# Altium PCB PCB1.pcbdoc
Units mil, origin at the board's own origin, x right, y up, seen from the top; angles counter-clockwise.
Board outline 3897.64 x 2283.46 mil, 4 copper layers (Top Layer, Inner1, Inner2, Bottom Layer), stack 62.447 mil thick; 82 components, 48 nets, 260 pads, 205 vias.
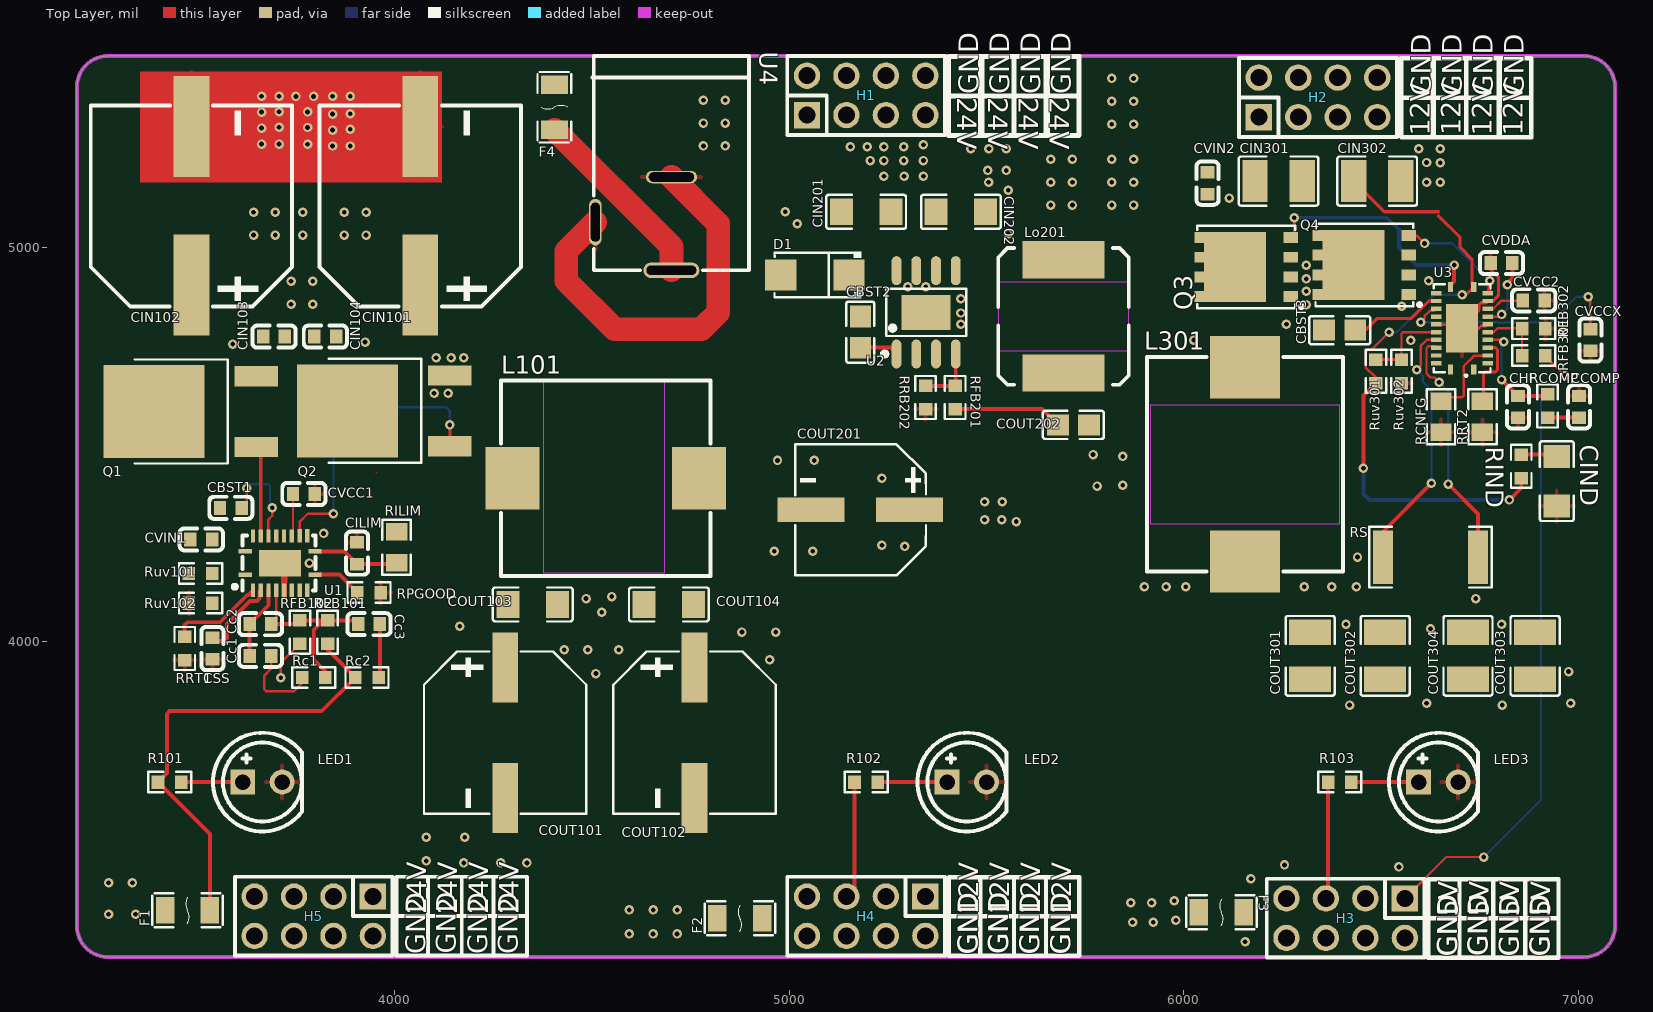
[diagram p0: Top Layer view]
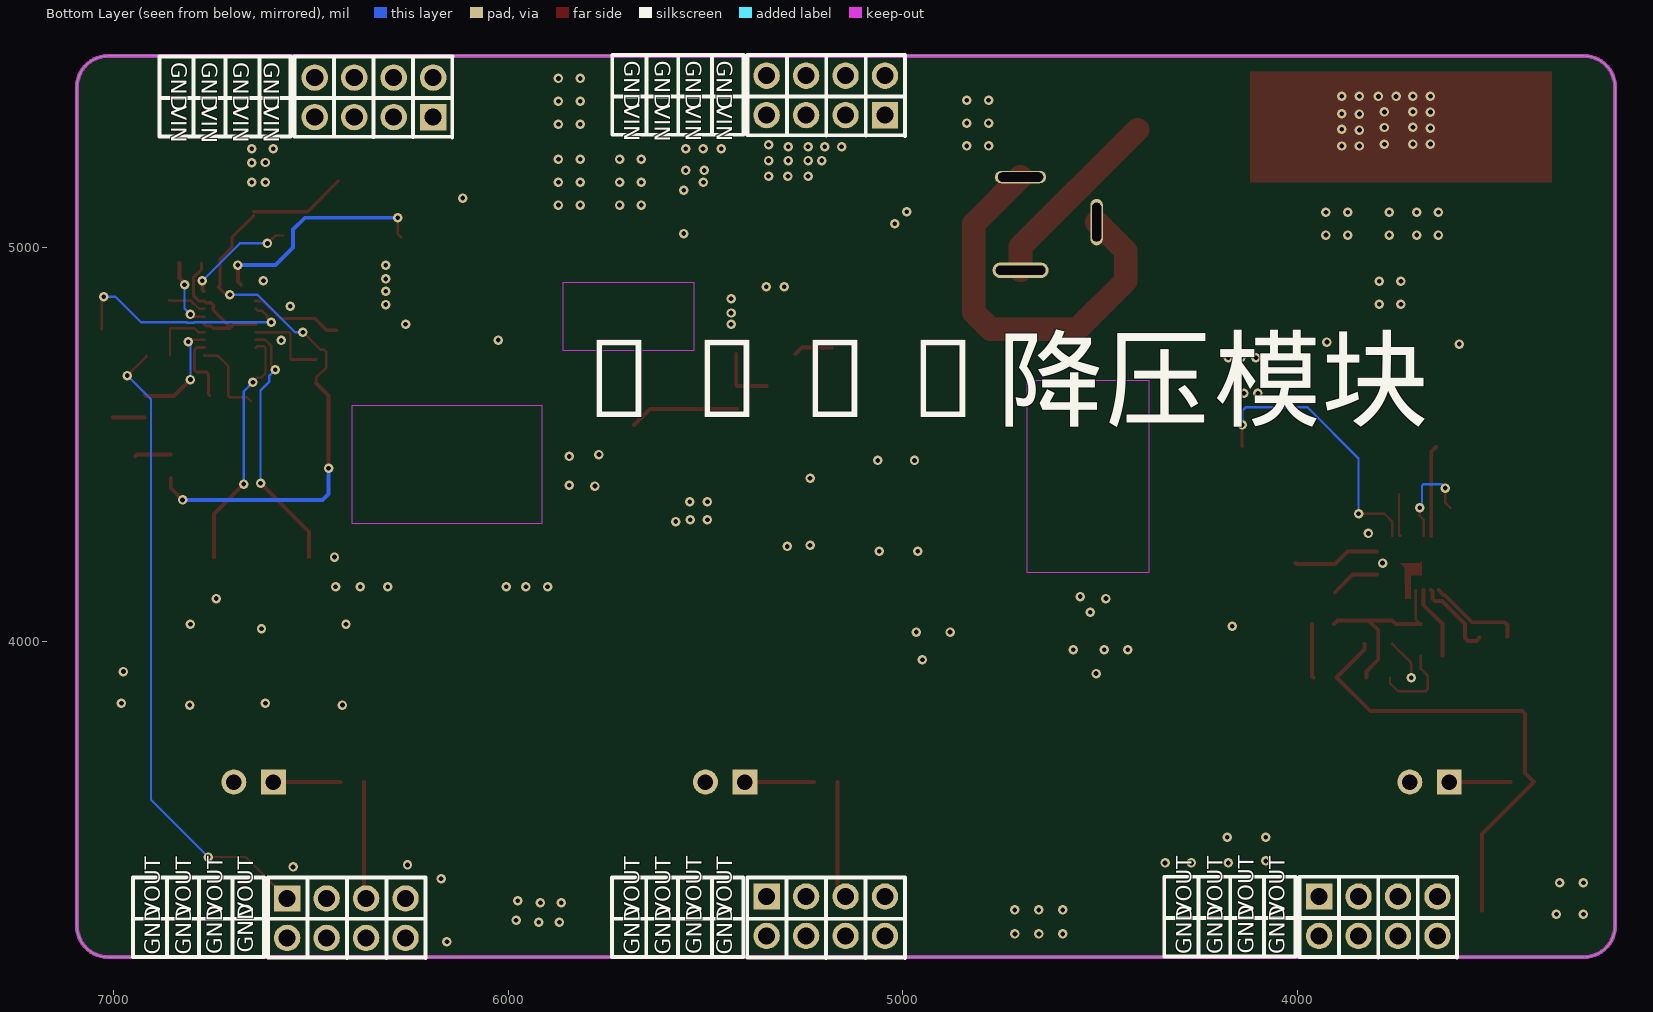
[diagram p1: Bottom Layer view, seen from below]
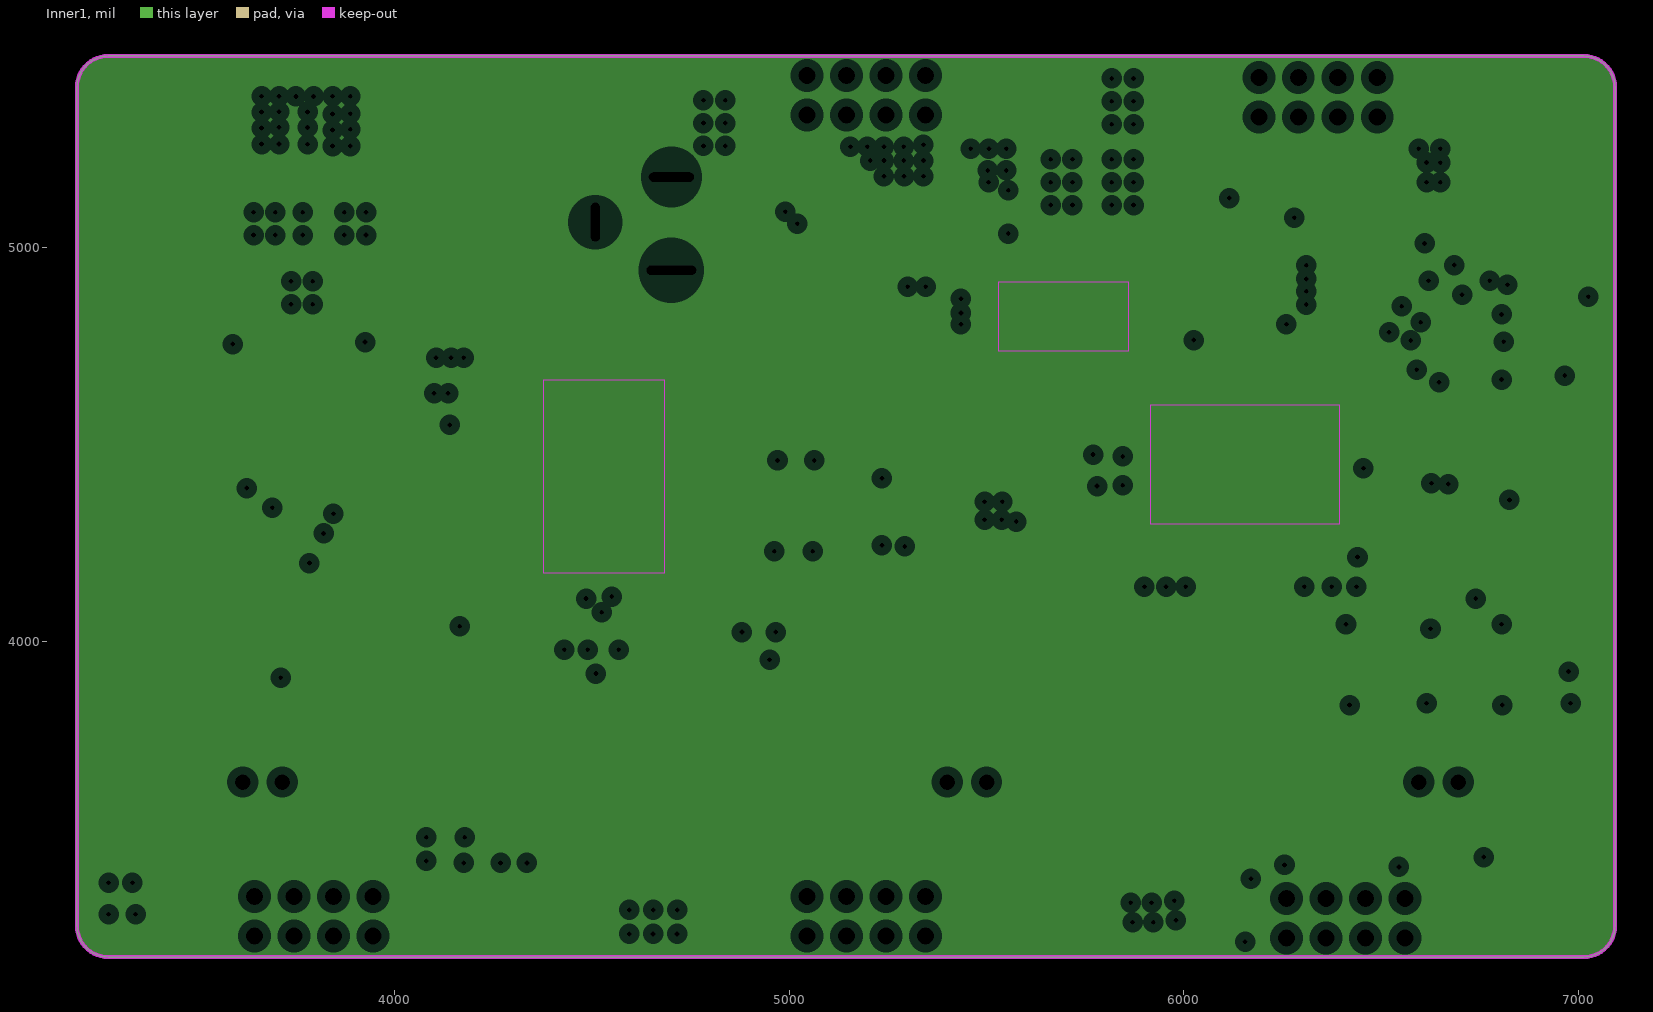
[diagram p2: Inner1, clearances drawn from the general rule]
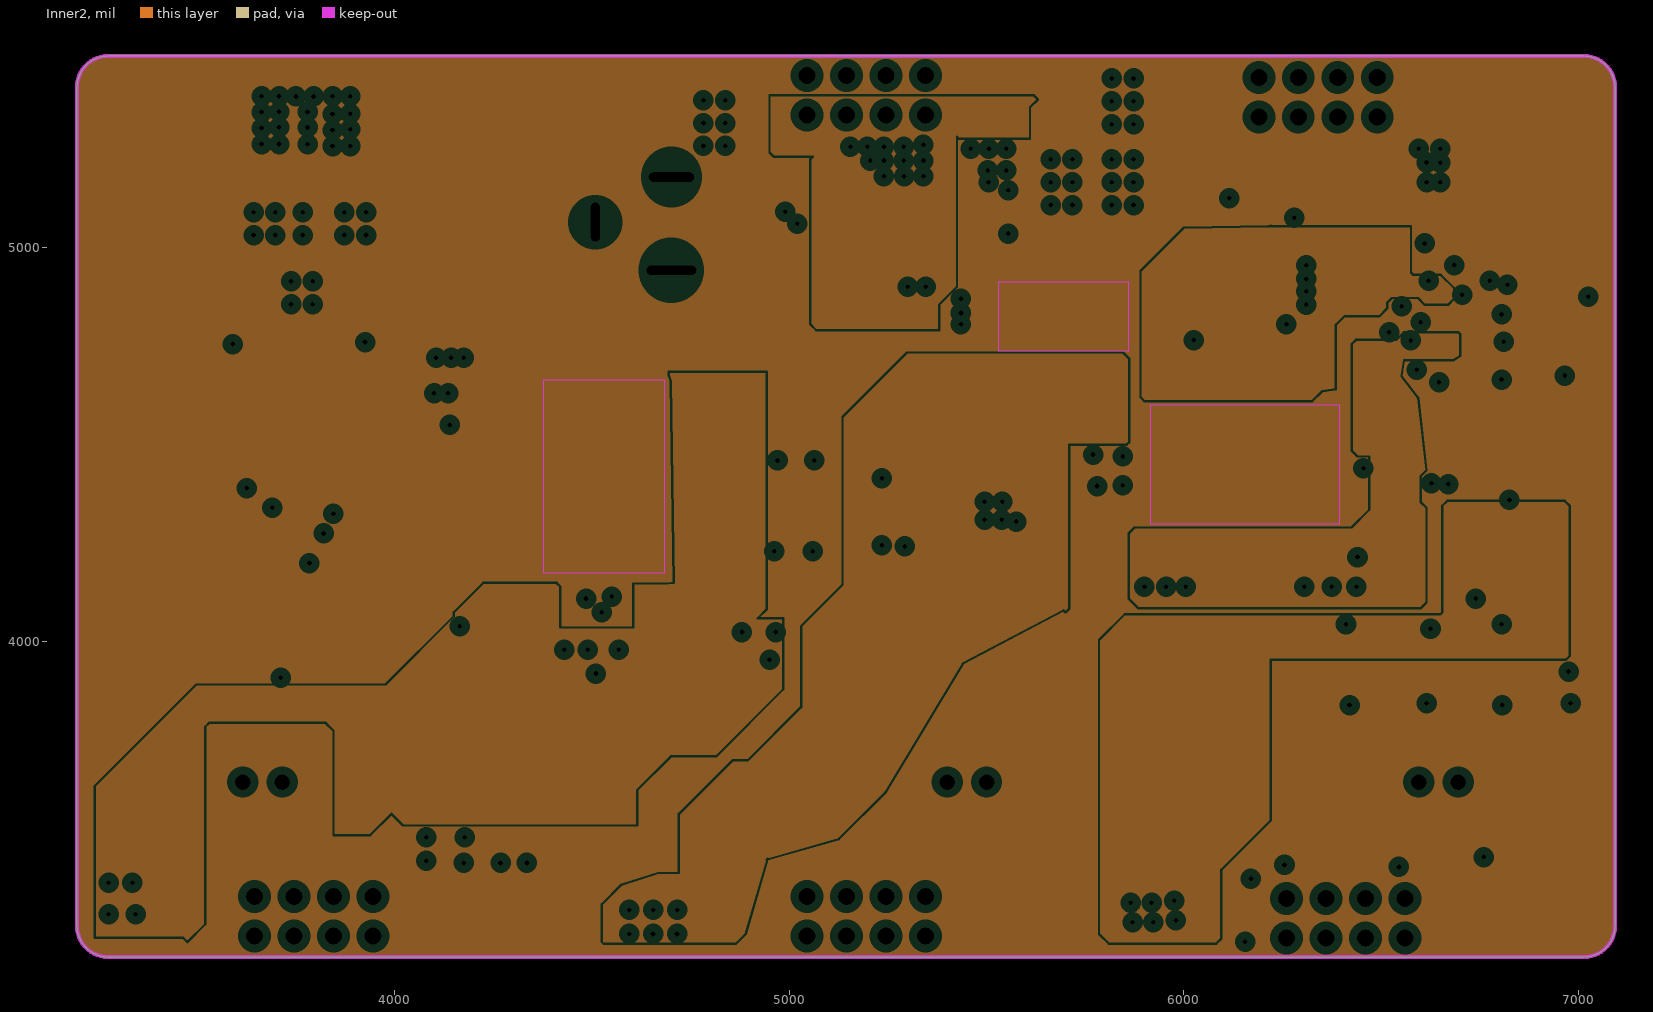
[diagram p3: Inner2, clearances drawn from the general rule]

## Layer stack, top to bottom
Top Layer: signal copper 1.378
Dielectric1: surface 8.283, 7628 RC49% 8.6mil, Dk 0
Inner1: plane copper 0.598
Dielectric2: surface 41.929, 1.1mm H/HOZ Copper, Dk 0
Inner2: plane copper 0.598
Dielectric3: surface 8.283, 7628 RC49% 8.6mil, Dk 0
Bottom Layer: signal copper 1.378

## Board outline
3273.74,5485 ccw(c3273.74,5406.26) 3195,5406.26 3195,3280.28 ccw(c3273.74,3280.28) 3273.74,3201.54 7013.9,3201.54 ccw(c7013.9,3280.28) 7092.64,3280.28 7092.64,5406.26 ccw(c7013.9,5406.26) 7013.9,5485 3273.74,5485

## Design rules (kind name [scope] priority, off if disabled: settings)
BoardOutlineClearance copperThickness2oz_1 [All] p2 off: genericclearance=7.99 ignorepadtopadclearanceinfootprint=FALSE except(0: Arc-SplitContinuation Track-SplitContinuation SMDPad-SplitContinuation THPad-SplitContinuation Via-SplitContinuation Fill-SplitContinuation Region-SplitContinuation Poly-SplitContinuation Text-SplitContinuation Hole-SplitContinuation; 5.98: Arc-CutoutEdge SMDPad-CutoutEdge THPad-CutoutEdge Via-CutoutEdge Fill-CutoutEdge Region-CutoutEdge Text-CutoutEdge; 6.93: Hole-OutlineEdge Hole-CutoutEdge; 10: Poly-OutlineEdge Poly-CutoutEdge; 11.81: Arc-OutlineEdge Track-OutlineEdge SMDPad-OutlineEdge THPad-OutlineEdge Via-OutlineEdge Fill-OutlineEdge Region-OutlineEdge Text-OutlineEdge Track-CutoutEdge)
BoardOutlineClearance copperThickness1oz_1 [All] p4: genericclearance=6 ignorepadtopadclearanceinfootprint=FALSE except(0: Arc-SplitContinuation Track-SplitContinuation SMDPad-SplitContinuation THPad-SplitContinuation Via-SplitContinuation Fill-SplitContinuation Region-SplitContinuation Poly-SplitContinuation Text-SplitContinuation Hole-SplitContinuation; 6: SMDPad-CutoutEdge THPad-CutoutEdge Via-CutoutEdge Fill-CutoutEdge Region-CutoutEdge Text-CutoutEdge; 6.93: Hole-OutlineEdge Hole-CutoutEdge; 10: Poly-OutlineEdge Poly-CutoutEdge; 11.8: Arc-OutlineEdge Track-OutlineEdge SMDPad-OutlineEdge THPad-OutlineEdge Via-OutlineEdge Fill-OutlineEdge Region-OutlineEdge Text-OutlineEdge; 11.81: Arc-CutoutEdge Track-CutoutEdge)
Clearance copperThickness2oz [All] p1 off: gap=7.99 ignorepadtopadclearanceinfootprint=FALSE except(5.98: SMDPad-Track SMDPad-SMDPad THPad-Track SMDPad-THPad THPad-THPad Track-Via SMDPad-Via THPad-Via Via-Via Fill-Track Region-Track Fill-SMDPad Region-SMDPad Fill-THPad Region-THPad Fill-Via Region-Via Fill-Fill Fill-Region Region-Region Arc-Track Arc-SMDPad Arc-THPad Arc-Via Fill-Arc Region-Arc Arc-Arc Text-Track SMDPad-Text Text-THPad Text-Via Fill-Text Region-Text Arc-Text Text-Text; 6.93: Hole-Track Hole-SMDPad Hole-THPad Hole-Via Fill-Hole Region-Hole Hole-Arc Hole-Text; 10: Poly-Track Poly-SMDPad Poly-THPad Poly-Via Poly-Fill Poly-Region Poly-Poly Poly-Arc Poly-Text Poly-Hole)
Clearance copperThickness1oz [All] p3: gap=6 ignorepadtopadclearanceinfootprint=FALSE except(0: Poly-Hole; 5.98: SMDPad-Track SMDPad-SMDPad THPad-Track SMDPad-THPad THPad-THPad SMDPad-Via THPad-Via Via-Via Fill-Track Region-Track Fill-SMDPad Region-SMDPad Fill-THPad Region-THPad Fill-Via Region-Via Fill-Fill Fill-Region Region-Region; 6.93: Hole-Track Hole-SMDPad Hole-THPad Hole-Via Fill-Hole Region-Hole Hole-Arc Hole-Text; 8: Poly-Track Poly-Via; 10: Poly-SMDPad Poly-THPad Poly-Fill Poly-Region Poly-Poly Poly-Arc Poly-Text)
Creepage creepage [All] p1: checkdistance=0 ignoreinternallayers=TRUE applytopolygonpour=TRUE
DiffPairsRouting differentialPair [All] p1: maxlimit=6 minlimit=6 mostfreqgap=6 toplayer_minwidth=5 toplayer_prefwidth=10 toplayer_maxwidth=100 toplayer_mingap=6 toplayer_prefgap=6 toplayer_maxgap=6 bottomlayer_minwidth=5 bottomlayer_prefwidth=10 bottomlayer_maxwidth=100 bottomlayer_mingap=6 bottomlayer_prefgap=6 bottomlayer_maxgap=6 maxuncoupledlength=10
HoleToHoleClearance otherClearance [All] p1: gap=11.81 allowstackedmicrovias=TRUE
Length netLength [All] p1: minlimit=0 maxlimit=0
MatchedLengths netLengthTolerance [All] p1: tolerance=1000
PasteMaskExpansion pasteMaskExpansion [All] p1: expansion=0
PlaneConnect innerPlane [All] p1: planeconnectstyle=Relief reliefexpansion=20 reliefentries=4 reliefconductorwidth=10 reliefairgap=10
PolygonConnect "copperRegion_Top Layer" [(InNet('GND')) And OnLayer('Top Layer')] p1: connectstyle=Relief reliefconductorwidth=10 reliefentries=4 polygonreliefangle="90 Angle" airgapwidth=10 via.connectstyle=Relief via.reliefconductorwidth=10 via.reliefentries=4 via.polygonreliefangle="90 Angle" via.airgapwidth=10
PolygonConnect "copperRegion_Bottom Layer" [(InNet('GND')) And OnLayer('Bottom Layer')] p2: connectstyle=Relief reliefconductorwidth=10 reliefentries=4 polygonreliefangle="90 Angle" airgapwidth=10 via.connectstyle=Relief via.reliefconductorwidth=10 via.reliefentries=4 via.polygonreliefangle="90 Angle" via.airgapwidth=10
PolygonConnect copperRegion_Inner1 [(InNet('GND')) And OnLayer('Inner1')] p3: connectstyle=Relief reliefconductorwidth=10 reliefentries=4 polygonreliefangle="90 Angle" airgapwidth=10 smdpad.connectstyle=Relief smdpad.reliefconductorwidth=10 smdpad.reliefentries=4 smdpad.polygonreliefangle="90 Angle" smdpad.airgapwidth=10 via.connectstyle=Relief via.reliefconductorwidth=10 via.reliefentries=4 via.polygonreliefangle="90 Angle" via.airgapwidth=10
PolygonConnect copperRegion_Inner2 [(InNet('GND')) And OnLayer('Inner2')] p4: connectstyle=Relief reliefconductorwidth=10 reliefentries=4 polygonreliefangle="90 Angle" airgapwidth=10 smdpad.connectstyle=Relief smdpad.reliefconductorwidth=10 smdpad.reliefentries=4 smdpad.polygonreliefangle="90 Angle" smdpad.airgapwidth=10 via.connectstyle=Relief via.reliefconductorwidth=10 via.reliefentries=4 via.polygonreliefangle="90 Angle" via.airgapwidth=10
PolygonConnect copperRegion [(InNet('GND'))] p5: connectstyle=Direct reliefconductorwidth=10 reliefentries=4 polygonreliefangle="90 Angle" airgapwidth=10 via.connectstyle=Relief via.reliefconductorwidth=10 via.reliefentries=4 via.polygonreliefangle="90 Angle" via.airgapwidth=10
RoutingVias viaSize [All] p1: holewidth=12.01 width=24.02 viastyle="Through Hole" minholewidth=11.81 minwidth=19.68 maxholewidth=248.03 maxwidth=393.7
SolderMaskExpansion solderMaskExpansion [IsVia] p1: expansion=-1000 istentingtop=TRUE
SolderMaskExpansion solderMaskExpansion [All] p2: expansion=2 istentingtop=FALSE
Width copperThickness2oz_2 [All] p1 off: maxlimit=100 minlimit=8 preferedwidth=10
Width copperThickness1oz_2 [All] p2: maxlimit=100 minlimit=5 preferedwidth=10

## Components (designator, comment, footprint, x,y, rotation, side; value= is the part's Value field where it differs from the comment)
CBST1 "100nF" C0603 3585,4340 r180 top
CBST2 "10nF" C0805 5180,4785 r90 top
CBST3 "100nF" C0805 6395,4790 r0 top
Cc1 "4.7nF" C0603 3660,3965 r180 top
Cc2 "82pF" C0603 3660,4045 r180 top
Cc3 "1.8nF" C0603 3935,4045 r0 top
CCOMP "8.2nF" C0603 7001.61,4595.77 r270 top
CHF "180pF" C0603 6846.61,4595.77 r90 top
CILIM "4.7nF" C0603 3905,4225 r90 top
CIN101 "100uF" CAP-SMD_BD12.5-L13.0-W13.0-LS13.7-FD 4065,5105 r90 top
CIN102 "100uF" CAP-SMD_BD12.5-L13.0-W13.0-LS13.7-FD 3485,5105 r90 top
CIN103 "100nF" C0603 3694.38,4773.86 r0 top
CIN104 "100nF" C0603 3824.38,4773.86 r180 top
CIN201 "22uf" C1206 5195,5090 r0 top
CIN202 "10uF" C1206 5435,5090 r180 top
CIN301 "22uF" C1210 6240,5168 r0 top
CIN302 "22uF" C1210 6490,5168 r180 top
CIND "47uF" C1206 6945,4407.3 r90 top
COUT101 "220uF" CAP-SMD_BD10.0-L10.3-W10.3-LS11.7-FD 4280,3770 r270 top
COUT102 "220uF" CAP-SMD_BD10.0-L10.3-W10.3-LS11.7-FD 4760,3770 r270 top
COUT103 "10uF" C1206 4350,4095 r180 top
COUT104 "10uF" C1206 4695,4095 r0 top
COUT201 "220uF" CAP-SMD_BD8.0-L8.3-W8.3-LS9.3-FD-A 5180,4335 r180 top
COUT202 "10uF" C0805 5720,4550 r180 top
COUT301 "47uF" C1210 6320,3965 r90 top
COUT302 "47uF" C1210 6510,3965 r90 top
COUT303 "47uF" C1210 6890,3965 r90 top
COUT304 "47uF" C1210 6720,3965 r90 top
CSS "47nF" C0603 3538.27,3983.49 r90 top
CVCC1 "2.2uF" C0603 3770,4375 r0 top
CVCC2 "2.2uF" C0603 6886.61,4865.77 r0 top
CVCCX "2.2uF" C0603 7030,4765 r90 top
CVDDA "100nF" C0603 6805,4960 r0 top
CVIN1 "100nF" C0603 3510,4260 r180 top
CVIN2 "22nF" C0603 6060,5162.57 r270 top
D1 "SS36" SMA_L4.3-W2.6-LS5.2-RD 5065,4930 r180 top
F1 "JFC1206-1300FS" F1206 3475,3320 r0 top
F2 "JFC1206-1300FS" F1206 4875,3300 r0 top
F3 "JFC1206-1300FS" F1206 6095,3315 r0 top
F4 "JFC1206-1300FS" F1206 4405,5355 r90 top
H1 "" HDR-TH_8P-P2.54-V-M-R2-C4-S2.54 5195,5385 r0 top
H2 "" HDR-TH_8P-P2.54-V-M-R2-C4-S2.54 6340,5380 r0 top
H3 "" HDR-TH_8P-P2.54-V-M-R2-C4-S2.54 6410,3300 r180 top
H4 "" HDR-TH_8P-P2.54-V-M-R2-C4-S2.54 5195,3305 r180 top
H5 "" HDR-TH_8P-P2.54-V-M-R2-C4-S2.54 3795,3305 r180 top
L101 "XR1250-4R7M" IND-SMD_L13.5-W12.6 4535,4415 r0 top
L301 "SMMS1360-2R2M" IND-SMD_L13.8-W12.6_SMMS1360 6155,4450 r270 top
LED1 "" LED-TH_5mm 3665,3645 r0 top
LED2 "" LED-TH_5mm 5450,3645 r0 top
LED3 "" LED-TH_5mm 6645,3645 r0 top
Lo201 "33uH" IND-SMD_L8.2-W8.2-LS8.6 5695,4825 r270 top
Q1 "NCE0110K" TO-252-2_L6.6-W6.1-P4.57-LS9.9-TL-CW 3519.38,4583.86 r180 top
Q2 "NCE0110K" TO-252-2_L6.6-W6.1-P4.57-LS9.9-TL-CW 4010.05,4585.37 r180 top
Q3 "BSC027N04LSG" PG-TDSON-8_L5.0-W6.0-P1.27-LS6.2-BL-EP 6157.77,4949.99 r90 top
Q4 "BSC027N04LSG" PG-TDSON-8_L5.0-W6.0-P1.27-LS6.2-BL-EP 6457.48,4955.13 r90 top
R101 "2K" R0603 3430,3645 r0 top
R102 "1K" R0603 5195,3645 r0 top
R103 "330Ω" R0603 6395,3645 r0 top
Rc1 "10.2K" R0603 3795,3910 r0 top
Rc2 "107Ω" R0603 3930,3910 r180 top
RCNFG "41.2kΩ" R0805 6651.61,4570.77 r90 top
RCOMP "5.23kΩ" R0603 6921.61,4597.96 r90 top
RFB101 "22.1K" R0603 3830,4025 r270 top
RFB102 "768Ω" R0603 3760,4025 r270 top
RFB201 "10kΩ" R0603 5420.5,4619.5 r270 top
RFB301 "78.7kΩ" R0603 6886.61,4725.77 r180 top
RFB302 "15kΩ" R0603 6886.61,4793.87 r180 top
RILIM "19.6K" R0805 4005,4240 r90 top
RIND "250mΩ" R0603 6855,4445 r270 top
RPGOOD "20K" R0603 3935,4125 r180 top
RRB202 "1.13kΩ" R0603 5345.5,4619.5 r90 top
RRT1 "24.9K" R0603 3468.27,3983.49 r90 top
RRT2 "73.2kΩ" R0805 6756.61,4570.77 r90 top
RS "2mΩ" R2512 6625,4215 r0 top
Ruv101 "402K" R0603 3508.27,4173.49 r180 top
Ruv102 "14.7K" R0603 3508.27,4098.49 r0 top
Ruv301 "100kΩ" R0603 6486.61,4685.77 r90 top
Ruv302 "10.5kΩ" R0603 6551.61,4685.77 r270 top
U1 "LM5145RGYR" VQFN-20_L4.5-W3.5-P0.50-BL-EP 3710,4200 r0 top
U2 "TPS5430DDA" ESOP-8_L4.9-W3.9-P1.27-LS6.0-BL-EP-2 5346.93,4835.27 r0 top
U3 "LM5148RGYR" VQFN-24_L5.5-W3.5-P0.50-BL-EP-2 6705,4795 r90 top
U4 "DC-S006A-D020-5A" CONN-TH_DC-S006A-D020-5A 4605,5060 r270 top

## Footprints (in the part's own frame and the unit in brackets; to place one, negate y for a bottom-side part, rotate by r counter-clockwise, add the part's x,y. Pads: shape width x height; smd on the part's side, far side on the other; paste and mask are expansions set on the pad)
C0603 [mm]
  rect 0.8x0.9 smd: 1(-0.7,0) 2(0.7,0)
  silkscreen extent -1.39,-0.71 1.39,0.71
C0805 [mm]
  rect 1.41x1.35 smd paste-100 mask+0.051: 1(-1,0) 2(1,0)
  silkscreen extent -1.96,-0.9 1.96,0.9
C1206 [mm]
  rect 1.485x1.728 smd paste-100 mask+0.051: 1(-1.593,0) 2(1.593,0)
  silkscreen extent -2.56,-1.09 2.56,1.09
C1210 [mm]
  rect 1.635x2.7 smd paste-100 mask+0.051: 1(-1.517,0) 2(1.517,0)
  silkscreen extent -2.56,-1.58 2.56,1.58
CAP-SMD_BD8.0-L8.3-W8.3-LS9.3-FD-A [mm]
  rect 4.3x1.6 smd: 1(-3.173,0) 2(3.173,0)
  silkscreen extent -4.23,-4.23 4.18,4.23
CAP-SMD_BD10.0-L10.3-W10.3-LS11.7-FD [mm]
  rect 4.5x1.65 smd: 1(-4.2,0) 2(4.2,0)
  silkscreen extent -5.23,-5.23 5.23,5.23
CAP-SMD_BD12.5-L13.0-W13.0-LS13.7-FD [mm]
  rect 6.5x2.3 smd: 1(-5.1,0) 2(5.1,0)
  silkscreen extent -6.48,-6.48 6.48,6.48
CONN-TH_DC-S006A-D020-5A [mm]
  oval 1x3.6 hole 0.6 slot 3.2 at 90 deg paste+0 mask+0.05: 1(3,2.45)
  oval 0.8x3.3 hole 0.6 slot 2.9 at 90 deg paste+0 mask+0.05: 2(-3,2.45)
  oval 3x0.8 hole 0.6 slot 2.5 at 0 deg paste+0 mask+0.05: 3(-0.1,-2.45)
  silkscreen extent -10.8,-2.63 3,7.45
ESOP-8_L4.9-W3.9-P1.27-LS6.0-BL-EP-2 [mm]
  oval 0.63x1.865 smd: 1(-1.905,-2.683) 2(-0.635,-2.683) 3(0.635,-2.683) 4(1.905,-2.683) 5(1.905,2.682) 6(0.635,2.682) 7(-0.635,2.682) 8(-1.905,2.682)
  rect 3.15x2.26 smd paste+0 mask+0.05: 9(0,0)
  silkscreen extent -2.82,-2.83 2.58,1.52
F1206 [mm]
  rect 1.19x1.728 smd: 1(-1.445,0) 2(1.445,0)
  silkscreen extent -2.27,-1.09 2.27,1.09
HDR-TH_8P-P2.54-V-M-R2-C4-S2.54 [mm]
  rect 1.7x1.7 hole 1.1: 1(-3.81,-1.27)
  round 1.7 hole 1.1: 2(-3.81,1.27) 3(-1.27,-1.27) 4(-1.27,1.27) 5(1.27,-1.27) 6(1.27,1.27) 7(3.81,-1.27) 8(3.81,1.27)
  silkscreen extent -5.08,-2.54 5.08,2.54
IND-SMD_L8.2-W8.2-LS8.6 [mm]
  rect 2.4x5.3 smd: 1(-3.638,0) 2(3.638,0)
  silkscreen extent -4.4,-4.2 4.4,4.2
IND-SMD_L13.5-W12.6 [mm]
  rect 3.5x4 smd: 1(-6,0) 2(6,0)
  silkscreen extent -6.75,-6.3 6.75,6.3
IND-SMD_L13.8-W12.6_SMMS1360 [mm]
  rect 4x4.5 smd: 1(-6.25,0) 2(6.25,0)
  silkscreen extent -6.9,-6.3 6.9,6.3
LED-TH_5mm [mm]
  rect 1.6x1.6 hole 1 paste+0 mask+0.051: 1(-1.27,0)
  round 1.6 hole 1 paste+0 mask+0.051: 2(1.27,0)
  silkscreen extent -3.17,-3.17 2.54,3.17
PG-TDSON-8_L5.0-W6.0-P1.27-LS6.2-BL-EP [mm]
  rect 0.7x0.925 smd paste-100 mask+0.051: 1(-1.905,-2.865) 2(-0.635,-2.865) 3(0.635,-2.865) 4(1.905,-2.865) 5(1.905,2.865) 6(0.635,2.865) 7(-0.635,2.865) 8(-1.905,2.865)
  rect 4.5x4 smd paste-100 mask+0.05: 9(0,0.705)
  silkscreen extent -2.66,-3.66 2.65,3.15
R0603 [mil]
  rect 31.75x34.02 smd paste-3937.01 mask+2: 1(-29.66,0) 2(29.66,0)
  silkscreen extent -55,-26 55,26
R0805 [mil]
  rect 44.59x54.21 smd paste-3937.01 mask+2: 1(-39.37,0) 2(39.37,0)
  silkscreen extent -69,-36 69,36
R2512 [mil]
  rect 50.49x136.06 smd paste-3937.01 mask+2: 1(-120.72,0) 2(120.72,0)
  silkscreen extent -155,-77 155,77
SMA_L4.3-W2.6-LS5.2-RD [mm]
  rect 2x2 smd: 1(-2.2,0) 2(2.2,0)
  silkscreen extent -2.98,-1.5 2.6,1.5
TO-252-2_L6.6-W6.1-P4.57-LS9.9-TL-CW [mm]
  rect 2.8x1.3 smd: 1(-3.292,2.273) 3(-3.292,-2.273)
  rect 6.5x6 smd: 2(3.292,0)
  silkscreen extent -1.46,-3.35 4.51,3.34
VQFN-20_L4.5-W3.5-P0.50-BL-EP [mm]
  rect 0.85x0.28 smd: 1(-2.25,-0.752) 10(2.25,-0.752) 11(2.25,0.748) 20(-2.25,0.75)
  rect 0.28x0.85 smd: 2(-1.749,-1.75) 3(-1.248,-1.75) 4(-0.749,-1.75) 5(-0.248,-1.75) 6(0.251,-1.75) 7(0.752,-1.75) 8(1.251,-1.75) 9(1.752,-1.75) 12(1.752,1.75) 13(1.251,1.75) 14(0.75,1.748) 15(0.25,1.748) 16(-0.25,1.748) 17(-0.75,1.748) 18(-1.25,1.748) 19(-1.75,1.748)
  rect 2.7x1.7 smd: 21(0,-0.002)
  silkscreen extent -3.05,-1.78 2.29,1.78
VQFN-24_L5.5-W3.5-P0.50-BL-EP-2 [mm]
  rect 0.665x0.336 smd: 1(-2.657,-0.75) 12(2.657,-0.75) 13(2.657,0.75) 24(-2.657,0.75)
  rect 0.28x0.665 smd: 2(-2.25,-1.657) 3(-1.75,-1.657) 4(-1.25,-1.657) 5(-0.75,-1.657) 6(-0.25,-1.657) 7(0.25,-1.657) 8(0.75,-1.657) 9(1.25,-1.657) 10(1.75,-1.657) 11(2.25,-1.657) 14(2.25,1.657) 15(1.75,1.657) 16(1.25,1.657) 17(0.75,1.657) 18(0.25,1.657) 19(-0.25,1.657) 20(-0.75,1.657) 21(-1.25,1.657) 22(-1.75,1.657) 23(-2.25,1.657)
  rect 3.1x2.05 smd: 25(0,0)
  silkscreen extent -3.12,-1.83 2.83,1.83

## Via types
v1: diameter 24.02, hole 12, Top Layer to Bottom Layer, 205 vias

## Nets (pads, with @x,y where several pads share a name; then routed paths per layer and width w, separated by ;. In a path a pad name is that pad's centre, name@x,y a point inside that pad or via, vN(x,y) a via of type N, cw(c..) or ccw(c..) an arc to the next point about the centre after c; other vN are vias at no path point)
$1N88: LED1.1 R101.2 | length 155.3
  Top Layer w10: R101.2 LED1.1
$1N109: COUT201.1 COUT202.2 F2.1 Lo201.2 RFB201.2 | length 276.6
  Top Layer w10: RFB201.2 5640.79,4589.84 COUT202.2
  other v1: 4594.3,3260 4655,3260 4715.7,3260 4594.65,3320.85 4655.35,3320.85 4716.04,3320.85 5292.77,4242.17 5235,4245 5235,4415
$1N113: LED2.1 R102.2 | length 175.3
  Top Layer w10: R102.2 LED2.1
$1N116: LED3.1 R103.2 | length 170.3
  Top Layer w10: R103.2 LED3.1
$1N123: Cc1.1 Rc1.1 | length 212.8
  Top Layer w6: Cc1.1 3687.56,3932.56 3670,3915 3670,3880 3675,3875 3745,3875 3765.34,3895.34 Rc1.1
$1N125: Cc3.2 Rc2.1 | length 136.2
  Top Layer w10: Rc2.1 3962.56,3912.9 Cc3.2
$1N132: COUT101.1 COUT102.1 COUT103.2 COUT104.2 F1.1 L101.2
  other v1: 3275,3310 3343.59,3310 3275,3390 3335.7,3390 4510,3920 4950,3955 4430,3980 4489.51,3980 4567.86,3980 4880,4025 4965.87,4025 4165,4040
$1N150: F4.1 U4.1 | length 479
  Top Layer w60: F4.1 4701.45,5001.65 U4.1
$2N64: CCOMP.2 RCOMP.1 | length 80
  Top Layer w10: RCOMP.1 7001.52,4568.3 CCOMP.2
$2N105: CIND.2 RIND.1 | length 91.9
  Top Layer w10: RIND.1 6940.34,4474.66 CIND.2
BOOT_24V: CBST2.1 U2.1 | length 98.5
  Top Layer w10: CBST2.1 5255.96,4745.63 U2.1
BST_48V: CBST1.1 U1.17 | length 254
  Top Layer w6: CBST1.1 3625,4352.44 v1(3625,4390) ; U1.17 3680,4269.29 3680,4310 3690,4320 v1(3690,4340)
  Bottom Layer w6: v1(3625,4390) 3635,4400 3680,4400 3684.24,4395.76 3684.24,4345.76 v1(3690,4340)
CBOOT: CBST3.2 U3.15 | length 236
  Top Layer w8: CBST3.2 6460,4790 6490,4820 6576.4,4820 6620.3,4863.9 U3.15
CNFG: RCNFG.2 U3.3 | length 210.6
  Top Layer w6: RCNFG.2 6661.47,4620 6705,4620 6709.24,4624.24 6709.24,4699.24 6735,4725 6769.16,4725 U3.3
COMP_48V: Cc1.2 Cc2.2 U1.4 | length 186
  Top Layer w10: Cc1.2 Cc2.2 3680.53,4093.09 U1.4
EN: Ruv301.2 Ruv302.1 U3.19 | length 220.8
  Top Layer w6: Ruv302.1 6551.61,4781.61 6555,4785 6639.59,4785 U3.19
  Top Layer w8: Ruv301.2 Ruv302.1
EN/UVLO_48V: Ruv101.1 Ruv102.2 U1.1
ENA: U2.5
EXTCOMP_12V: CHF.2 RCOMP.2 U3.5 | length 275.9
  Top Layer w6: U3.5 6805.73,4765.47 v1(6810.6,4760.6)
  Top Layer w10: v1(6805,4665) CHF.2@6846.61,4623.39 ; CHF.2 6917.31,4623.33 RCOMP.2
  Bottom Layer w6: v1(6805,4665) 6805,4755 v1(6810.6,4760.6)
FB_12V: RFB301.2 RFB302.2 U3.6 | length 159.3
  Top Layer w6: U3.6 6785.15,4785.15 6795,4795 6855.81,4795 RFB302.2 RFB301.2
FB_48V: Cc2.1 Cc3.1 Rc1.2 RFB101.1 RFB102.1 U1.5 | length 486.4
  Top Layer w6: Cc2.1 3700.22,4057.66 U1.5
  Top Layer w10: Cc2.1 3750.34,4045 RFB102.1 RFB101.1@3819.66,4054.66 ; Rc1.2 3824.66,3925.34 3795,3955 3795,4030 RFB101.1@3819.66,4054.66 ; Cc3.1 3897.78,4054.66 RFB101.1 RFB101.1@3819.66,4054.66
GND: CCOMP.1 CHF.1 CILIM.2 CIN101.2 CIN102.2 CIN103.1 CIN104.1 CIN201.1 CIN202.1 CIN301.1 CIN302.1 CIND.1 COUT101.2 COUT102.2 COUT103.1 COUT104.1 COUT201.2 COUT202.1 COUT301.1 COUT302.1 COUT303.1 COUT304.1 CSS.1 CVCC1.2 CVCC2.2 CVCCX.1 CVDDA.1 CVIN2.2 D1.2 H1.2 H1.4 H1.6 H1.8 H2.2 H2.4 H2.6 H2.8 H3.2 H3.4 H3.6 H3.8 H4.2 H4.4 H4.6 H4.8 H5.2 H5.4 H5.6 H5.8 LED1.2 LED2.2 LED3.2 Q2.3 Q4.1 Q4.2 Q4.3 RCNFG.1 RFB102.2 RFB302.1 RPGOOD.1 RRB202.1 RRT1.1 RRT2.1 Ruv102.1 Ruv302.2 U1.6 U1.12 U1.15 U1.21 U2.6 U2.9 U3.7 U3.10 U3.18 U3.25 U4.2 U4.3 | length 1496.4
  Top Layer w6: v1(3711.15,3909.56) 3711.15,3942.42 3712.29,3943.56 3712.29,3947.63 RFB102.2
  Top Layer w8: U3.18 6695.16,4804.84 U3.25 ; U3.7 6766.07,4800.65 6753.03,4800.65 6747.37,4794.99 U3.25 ; CVDDA.1 6777.44,4943.68 6797.01,4924.12 6797.01,4877.01 6783.9,4863.9 U3.10 6766.06,4859.7 6753.03,4859.7 6747.18,4853.85 6747.18,4840.82 6705.01,4798.65 U3.25
  Top Layer w60: U4.3 4435,4990.39 4435,4915 4557.43,4792.57 4777.57,4792.57 4820,4835 4820,5059.56 U4.2
  other v1: 4175,3440 4268.53,3440 4335.38,3440 4080,3445 4080,3505 4177.64,3505 6420,3840 6806.81,3840 6615,3845 6980,3845 6975,3925 4525,4075 4485,4110 4550,4115 3783.98,4200 4961.85,4230 5059.75,4230 3820,4275 5575,4305 5495,4310 5538.76,4310 5495,4355 5540,4355 5780,4395 5845,4396.86 4970.25,4460 5063.15,4460 5845,4470 5770,4475 4100,4630 4135.49,4630 4105,4720 4143,4720 4175,4720 3590,4755 3925,4760 5435,4805.32 5435,4833.59 6552.1,4850.88 5435,4870 5555,5035 5020,5060 4990,5090 5662.5,5107.1 5717.5,5107.1 5817.5,5107.1 5872.5,5107.1 6115,5125 5555,5145 5505,5165 5662.5,5165 5717.5,5165 5817.5,5165 5872.5,5165 6615,5165 6650,5165 5503.33,5195 5550,5195 6650,5214.43 6615,5215 5662.5,5222.9 5717.5,5222.9 5817.5,5222.9 5872.5,5222.9 5460,5250 5505.97,5250 5550,5250 6595,5250 6650,5250 3842.77,5256.8 3887.23,5256.8 4782.5,5257.1 4837.5,5257.1 3779.47,5261.11 3662.77,5261.8 3707.23,5261.8 3842.77,5297.27 3887.23,5299.41 3662.77,5302.27 3707.23,5304.41 3779.47,5303.71 5817.5,5312.1 5872.5,5312.1 4782.5,5315 4837.5,5315 3842.77,5337.73 3887.23,5338.8 3662.77,5342.73 3779.47,5343.11 3707.23,5343.8 5817.5,5370 5872.5,5370 4782.5,5372.9 4837.5,5372.9 3750,5382.5 3794.47,5382.5 3662.77,5383.2 3707.23,5383.2 3842.77,5383.2 3887.23,5383.2 5817.5,5427.9 5872.5,5427.9
HO_12V: Q3.4 U3.13 | length 587.9
  Top Layer w6: Q3.4 6280,5034.42 v1(6280,5075)
  Top Layer w10: U3.13@6677.08,4905.4 6685,4913.31 v1(6685,4955)
  Bottom Layer w10: v1(6280,5075) 6515,5075 6545,5045 6545,5000 6590,4955 v1(6685,4955)
HO_48V: Q1.1 U1.18 | length 230.4
  Top Layer w10: Q1.1 3660.79,4482.57 U1.18
ILIM_48V: CILIM.1 RILIM.1 U1.11 | length 221
  Top Layer w10: U1.11 3872.99,4229.45 CILIM.1 4001.81,4197.44 RILIM.1
ISNS+: L301.2 RS.1 U3.20 | length 651.9
  Top Layer w6: v1(6590,4690) 6600,4700 6600,4750 6615.47,4765.47 U3.20
  Top Layer w10: RS.1 6504.28,4279.28 v1(6627.5,4402.5)
  Bottom Layer w6: v1(6590,4690) 6605,4675 6605,4660 6627.5,4637.5 v1(6627.5,4402.5)
  other v1: 5900,4140 5955,4140 6005,4140 6305,4140 6375,4140 6437.24,4140 6440,4215 6575,4763.99
LO_12V: Q4.4 U3.11 | length 279.4
  Top Layer w6: Q4.4 6589.87,5030.13 v1(6610,5010)
  Top Layer w10: 6771.86,4889.35 6775,4892.48 v1(6775,4915)
  Bottom Layer w6: v1(6610,5010) 6680,5010 v1(6775,4915)
LO_48V: Q2.1 U1.13 | length 711.9
  Top Layer w6: U1.13 3759.27,4304.27 3780,4325 v1(3845,4325)
  Top Layer w8: Q2.1 4140,4496.24 v1(4140,4550)
  Bottom Layer w6: v1(3845,4325) 3845,4465 3975,4595 4130,4595 4140,4585 v1(4140,4550)
NC: U1.16
PGOOD_48V: RPGOOD.2 U1.10 | length 125.6
  Top Layer w10: U1.10 3859.95,4170.39 RPGOOD.2
PH: CBST2.2 D1.1 Lo201.1 U2.8
RT_12V: RRT2.2 U3.4 | length 172.2
  Top Layer w8: RRT2.2@6756.61,4625.14 6759.34,4627.88 6759.34,4678.69 6765,4684.34 6789.34,4684.34 6795,4690 6795,4740 6789.22,4745.78 U3.4
RT_48V: RRT1.2 U1.2 | length 239.7
  Top Layer w10: RRT1.2 3467.93,4013.5 3467.93,4042.93 3475,4050 3557.12,4050 3626.51,4119.38 3629.44,4119.38 U1.2
SS/TRK_48V: CSS.2 U1.3 | length 210.3
  Top Layer w10: CSS.2 3546.4,4002.93 3567.93,4002.93 3575,4010 3575,4045.25 3633.13,4103.38 3651.22,4103.38 3657.66,4109.82 3657.66,4127.91 U1.3
SW_12V: CBST3.1 L301.1 Q3.1 Q3.2 Q3.3 Q4.5 Q4.6 Q4.7 Q4.8 Q4.9 U3.14
  other v1: 6025,4765 6260,4805 6310,4855 6310,4888.63 6620,4915 6310,4919.91 6310,4954.29
SW_48V: CBST1.2 L101.1 Q1.3 Q2.2 RILIM.2 U1.19
VCC_12V: CVCC2.1 U3.9 | length 97.7
  Top Layer w6: U3.9 6784.2,4844.2 6805,4865 6858.28,4865 CVCC2.1
VCC_48V: CVCC1.1 U1.14 | length 107.4
  Top Layer w6: U1.14 3742.44,4271.73 CVCC1.1
VCCX_12V: CVCCX.2 U3.16 | length 594.7
  Top Layer w6: v1(6600,4810) 6610,4820 6610,4826.09 6622.93,4839.02 6634.56,4839.02 U3.16 ; v1(7025,4875) 7030,4870 CVCCX.2
  Bottom Layer w6: v1(6600,4810) 6795.29,4810 6796.3,4808.99 6813.7,4808.99 6814.71,4810 6930,4810 6995,4875 v1(7025,4875)
VDDA_12V: CVDDA.2 U3.8 | length 178.4
  Top Layer w6: U3.8 6799.52,4824.52 v1(6805,4830)
  Top Layer w10: v1(6820,4905) 6820,4910 6832.56,4922.56 CVDDA.2
  Bottom Layer w6: v1(6805,4830) 6820,4845 v1(6820,4905)
VIN_12V: CIN301.2 CIN302.2 CVIN2.1 H2.1 H2.3 H2.5 H2.7 Q3.5 Q3.6 Q3.7 Q3.8 Q3.9 RIND.2 Ruv301.1 U3.12 | length 1634.5
  Top Layer w6: Ruv301.1 6486.61,4669.84 6460.61,4695.83 6460.61,4735.03 6465.88,4740.29 6475.29,4740.29 v1(6520,4785)
  Top Layer w8: CIN302.2 6508.26,5090 6645,5090 ; 6645,5080 6700,5025 6700,5000 6730,4970 6730,4904.16 U3.12 6714.91,4880 v1(6705,4880)
  Top Layer w10: v1(6455,4440) 6455,4624.5 Ruv301.1 ; v1(6825,4360) 6855,4390 RIND.2
  Bottom Layer w6: v1(6520,4785) 6540,4785 6635,4880 v1(6705,4880)
  Bottom Layer w10: v1(6455,4440) 6455,4375 6470,4360 v1(6825,4360)
VIN_24V: CIN201.2 CIN202.2 H1.1 H1.3 H1.5 H1.7 U2.7
  other v1: 5300,4900 5345.63,4900.17 5240,5180 5290.86,5180 5340,5180 5205,5220 5240,5220 5290,5220 5340,5220 5155,5255 5197.67,5255 5240,5255 5290,5255 5340,5259.85
VIN_48V: CIN101.1 CIN102.1 CIN103.2 CIN104.2 CVIN1.1 CVIN1.2 F4.2 Q1.2 Ruv101.2 U1.20
  other v1: 3737.5,4856.05 3792.5,4856.05 3737.5,4913.95 3792.5,4913.95 3642.5,5031.05 3697.5,5031.05 3767.5,5031.05 3872.5,5031.05 3927.5,5031.05 3642.5,5088.95 3697.5,5088.95 3767.5,5088.95 3872.5,5088.95 3927.5,5088.95
VOUT: COUT301.2 COUT302.2 COUT303.2 COUT304.2 F3.1 RS.2 U3.21 | length 617.9
  Top Layer w6: U3.21 6636.29,4749.24 6619.24,4749.24 6615,4745 6615,4680 6625,4670 6635,4670 v1(6646.58,4658.42)
  Top Layer w10: v1(6670,4400) 6745.72,4324.28 RS.2
  Bottom Layer w6: v1(6646.58,4658.42) 6670,4635 v1(6670,4400)
  other v1: 5870,3290 5922.5,3290 5980,3295 5865.55,3339.34 5918.05,3339.34 5975.55,3344.34 6625,4033.31 6410.87,4045 6805,4045 6740,4110
VOUT_5V: F3.2 H3.1 H3.3 H3.5 H3.7 R103.1 RFB301.1 | length 1916.6
  Top Layer w6: H3.1 6665,3455 v1(6760,3455) ; RFB301.1 6916.27,4723.73 v1(6965,4675)
  Top Layer w10: H3.5 6365.34,3355.34 R103.1
  Bottom Layer w6: v1(6760,3455) 6905,3600 6905,4615 v1(6965,4675)
  other v1: 6155,3240 6170,3400 6545,3430 6255,3435
VOUT_12V: F2.2 H4.1 H4.3 H4.5 H4.7 R102.1 | length 298.4
  Top Layer w10: H4.5 5165.34,3375.34 R102.1
VOUT_24V: F1.2 H5.1 H5.3 H5.5 H5.7 R101.1 Rc2.2 RFB101.2 | length 1191.8
  Top Layer w10: F1.2 3531.89,3513.45 R101.1 3422.93,3667.59 3422.93,3817.93 3430,3825 3815.34,3825 Rc2.2 3830,3980.34 RFB101.2
VSNS: RFB201.1 RRB202.2 U2.4 | length 156.1
  Top Layer w10: RRB202.2 RFB201.1 5421.93,4650.6 U2.4
pads on no net: U1.7 U1.8 U1.9 U2.2 U2.3 U3.1 U3.2 U3.17 U3.22 U3.23 U3.24

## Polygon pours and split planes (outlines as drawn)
VIN_48V on Top Layer (solid, remove dead copper, pour order 0): 4465,5460 4465,5360.79 4454.21,5350 4330,5350 4325,5355 4290,5320 4290,4750 3950,4750 3943.67,4828.67 3860,4820 3820,4820 3820,4731.34 3691.34,4731.34 3689.38,4729.38 3689.38,4821.24 3606.24,4821.24 3540,4755 3540,4425 3515,4400 3445,4400 3445,4300 3450,4295 3555,4295 3591.16,4258.84 3607.92,4250 3617.22,4240.7 3645,4240 3645,4211.65 3571.65,4211.65 3565,4205 3560,4210 3245,4210 3245,4730 3240,4735 3240,5120 3245,5125 3610,5125 3615,5130 4115,5130 4150,5165 4150,5425 4170,5445 4450,5445
VOUT_24V on Top Layer (solid, remove dead copper, pour order 98): 3495,3410 3512.74,3427.74 3995,3427.74 4012.77,3409.97 4012.77,3305 3620,3305 3580,3265 3505,3265 3495,3275
GND on Top Layer (solid, remove dead copper, pour order 100): 4065,4735 4205,4735 4205,4680 4200,4675 4200,4650 4165,4615 4080,4615 4080,4720
GND on Top Layer (solid, remove dead copper, pour order 104): 3610,4815 3680,4815 3685,4810 3685,4740 3680,4735 3585,4735 3570.8,4749.2 3577.1,4782.1
GND on Top Layer (solid, remove dead copper, pour order 106): 3915,4811.82 3915,4800 3925,4790 3940,4772.98 3940,4750 3920,4730 3830,4730 3830,4811.82
GND on Top Layer (solid, remove dead copper, pour order 112): 3759.27,4215.62 3804.38,4215.62 3810,4210 3810,4185 3765,4185 3760,4180 3760,4214.89
GND on Top Layer (solid, remove dead copper, pour order 120): 3615,3290 3980,3290 3980,3285 3985,3280 3985,3220 3980,3215 3610,3215 3605,3220 3605,3280
VIN_48V on Top Layer (solid, remove dead copper, pour order 122): 3459.25,4287.95 3459.25,4147.49 3508.27,4147.49 3508.27,4287.95
EN/UVLO_48V on Top Layer (solid, remove dead copper, pour order 124): 3520,4200 3573.04,4200 3573.04,4186.96 3575,4185 3601.46,4185 3601.46,4183.54 3605,4180 3641.32,4180 3641.32,4156.49 3601.49,4156.49 3600,4155 3575,4155 3575,4085 3570,4080 3560,4080 3555,4075 3508.27,4075 3508.27,4123.27 3515,4130 3515,4195
VIN_24V on Top Layer (solid, remove dead copper, pour order 126): 4974.23,5385 5385,5385 5390,5390 5390,5185 5395,5180 5430,5180 5435,5175 5435,5055 5425,5045 5351.99,5045 5340.07,5046.98 5318.73,5040.51 5308.19,5036.23 5292.55,5045 5202.35,5045 5190,5165 5195,5170 5105,5260 4970,5260 4974.23,5264.23
PH on Top Layer (solid, remove dead copper, pour order 128): 5065,5008.12 5176.88,5008.12 5180,5005 5180,4990 5205,4965 5225,4965 5245,4985 5290,4985 5283.18,4901.82 5245,4890 5210,4855 5210,4795.87 5209.36,4790 5095,4790 5095,4795.4 5090,4850 5065,4875
VOUT_12V on Top Layer (solid, remove dead copper, pour order 134): 4885,3420 4910,3445 5400,3445 5400,3300 5395,3305 5025.87,3305 4968.13,3228.27 4885,3228.27
GND on Top Layer (solid, remove dead copper, pour order 136): 5035,3295 5385,3295 5385,3215 5010,3215 5005,3220 5005,3280 5020,3280
GND on Top Layer (solid, remove dead copper, pour order 138): 5005,5475 5395,5475 5395,5395 5390,5390 5020,5390 5005,5405
GND on Top Layer (solid, remove dead copper, pour order 142): 5261.93,4789.36 5280.32,4807.75 5280.32,4885 5366.67,4885 5355,4915 5356.23,4985 5395,4985 5395,4900 5399.83,4895.17 5455.17,4895.17 5460,4900 5460,4789.36
GND on Top Layer (solid, remove dead copper, pour order 148): 5455,5160 5455,5020 5570,5020 5570,5160
PH on Top Layer (solid, remove dead copper, pour order 150): 5850,5020 5850,4915 5500,4915 5500,4935 5445,4990 5290,4990 5290,4915 5285,4910 5235,4910 5235,5015 5565,5015 5570,5010 5591.07,5031.07 5602.14,5020
VIN_24V on Top Layer (solid, remove dead copper, pour order 152): 5286.64,4895.17 5285,4896.81 5285,4905.6 5295.86,4916.46 5295.86,4987.37 5349.08,4987.37 5349.08,4915.92 5360,4905 5360,4900.99 5360.6,4900.39 5360.6,4890.6 5354.62,4884.62 5340.38,4884.62 5335,4890 5330.71,4890 5329.59,4891.12 5329.59,4900 5315,4900 5315,4892.25 5307.75,4885 5295,4885 5286.64,4893.36
VOUT on Top Layer (solid, remove dead copper, pour order 166): 5855,3375 6090,3375 6095,3370 6095,3230 6070,3205 5850,3205 5855,3210
VOUT_5V on Top Layer (solid, remove dead copper, pour order 172): 6115,3410 6180,3475 6575,3475 6605,3445 6605,3305 6600,3310 6215,3310 6215,3220 6205,3210 6200,3215 6120,3215 6115,3220
GND on Top Layer (solid, remove dead copper, pour order 174): 6223.96,3300 6598.47,3300 6598.47,3211.53 6600,3210 6230,3210 6225,3215 6225,3230 6220,3235 6220,3270 6225,3275 6223.96,3276.04
GND on Top Layer (solid, remove dead copper, pour order 176): 6015,5085 6015,5150 6020,5155 6125,5155 6135,5165 6135,5245 6140,5240 6230,5240 6230,5090 6225,5085
GND on Top Layer (solid, remove dead copper, pour order 178): 6550.03,5400.29 6150,5400.29 6150,5470 6550,5470 6555,5475 6695,5335 6695,5100 6515,5100 6505,5110 6505,5220 6565,5280 6570,5280 6570,5379.05 6550.03,5399.02
GND on Top Layer (solid, remove dead copper, pour order 180): 5465,5120 5465,5185 5430,5220 5430,5400 5425,5405 5295,5405 5295,5475 5540,5475 5570,5445 5570,5125 5565,5120
GND on Top Layer (solid, remove dead copper, pour order 182): 6540,4995 6595,4995 6595,4835 6537.54,4835
VIN_12V on Top Layer (solid, remove dead copper, pour order 184): 5965,5395 6531.84,5395 6531.84,5307.05 6519.79,5295 6515,5295 6485,5265 6485,5120 6490,5115 6493.97,5115 6511.9,5097.07 6567.93,5097.07 6570,5095 6690,5095 6710,5075 6710,5010 6740,4980 6745.2,4892.68 6717.67,4892.68 6720,4945 6715,4950 6715,4965 6661,5019 6630,5035 6585,5080 6350,5080 6340,5090 6315,5090 6310,5095 6275,5095 6231.31,5051.31 6230,4850 5945,4850 5925,4870 5925,5025 5980,5080 6225,5080 6235,5090 6235,5260.18 6230.18,5265 6125,5265 6125,5180 6115,5170 5985,5170 5980,5165 5980,5380
SW_12V on Top Layer (solid, remove dead copper, pour order 188): 6614.15,4873.04 6606.39,4883.61 6606.39,4927.47 6660,4927.47 6660,4873.04
SW_48V on Top Layer (solid, remove dead copper, pour order 190): 3650,4245 3620,4245 3575,4290 3558.22,4312.06 3492.94,4312.06 3475,4330 3475,4370 3484.72,4379.72 3590,4379.72 3590,4300 3650,4300
SW_48V on Top Layer (solid, remove dead copper, pour order 192): 3954.67,4430 3953.33,4429.25 3953.27,4430
SW_48V on Top Layer (solid, remove dead copper, pour order 194): 3960,4340 3953.33,4429.25 3950,4427.39 3733.07,4445 3720,4458.07 3712.23,4551.47 3590,4551.47 3580,4465 3624.09,4445 3575,4330 3570,4325 3515,4325 3520,4330 3520,4375 3545,4400 3545,4420 3555,4430 3555,4690 3590,4725 4050,4725 4065,4710 4065,4470 4070,4465 4200,4465 4220,4485 4220,4670 4226.97,4663.03 4359.53,4663.03 4367.89,4654.67 4367.89,4166.97 4360.92,4160 4185,4160 4185,4185 4125,4245 3950,4245 3950,4330
$1N132 on Top Layer (solid, remove dead copper, pour order 196): 5045,3785 4130,3785 4130,4140 4140,4150 4340,4150 4350,4140 4350,4040 4355,4035 4675,4035 4690,4050 4690,4710 4890,4710 4849.92,4669.92 4849.92,4166.97 4883.03,4166.97 5045,4005
$1N132 on Top Layer (solid, remove dead copper, pour order 198): 3240,3425 3460,3425 3460,3255 3455,3250 3255,3250 3235,3270 3240,3275
GND on Top Layer (solid, remove dead copper, pour order 200): 4370,4145 4670,4145 4675,4150 4675,4050 4665,4040 4385,4040 4375,4050 4375,4140
GND on Top Layer (solid, remove dead copper, pour order 202): 4015,3740 5040,3740 5045,3735 5035,3725 5035,3480 4380,3480 4375,3485 4375,3220 4370,3215 3885,3215 3880,3220 3900,3240 3900,3285 3905,3290 4015,3290
GND on Top Layer (solid, remove dead copper, pour order 204): 4915,4840 4930,4855 4930,5150 4935.27,5155.27 5161.53,5155.27 5180,5136.81 5180,5030 5175,5035 5050,5035 5050,4860 5030,4840
$1N109 on Top Layer (solid, remove dead copper, pour order 206): 5505,4735 5850,4735 5860,4725 5860,4610 5720,4610 5710,4600 5710,4485 5715,4480 5665,4430 5665,4190 5218.62,4190 5180,4228.62 5180,4505 5215,4540 5365,4540 5370,4535 5385.06,4550.06 5507.56,4540 5507.56,4572.47 5505,4621.68
GND on Top Layer (solid, remove dead copper, pour order 208): 4925,4530 5150,4530 5155,4525 5155,4195 5125,4165 4945,4165 4920,4190 4925,4195
$1N109 on Top Layer (solid, remove dead copper, pour order 210): 4565,3370 4850,3370 4850,3230 4570,3230 4560,3240 4565,3245
GND on Top Layer (solid, remove dead copper, pour order 212): 5720,4592.48 5877.52,4592.48 5880,4590 5880,4375 5855,4350 5735,4350 5725,4360 5725,4587.48
SW_12V on Top Layer (solid, remove dead copper, pour order 214): 6245,4995 6315,4995 6315,5040 6330,5055 6510.48,5055 6525,5040.48 6525,4850 6520,4845 6393.33,4845 6393.33,4746.31 6419.64,4720 6445,4720 6445,4610 5890,4610 5890,4775 5910,4795 6205,4795 6240,4830 6240,4861.08 6245,4866.08
ISNS+ on Top Layer (solid, remove dead copper, pour order 216): 5875,4290 6600,4290 6605,4295 6605,4105 6610,4100 5855,4100 5845,4090 5845,4260
VOUT on Top Layer (solid, remove dead copper, pour order 218): 6645,4315 6815,4315 6815,4115 6830,4100 7005,4100 7015,4090 7015,3977.82 7027.82,3965 6245,3965 6220,3990 6220,4055 6240.7,4075.7 6630.7,4075.7 6650,4095 6650,4310
GND on Top Layer (solid, remove dead copper, pour order 220): 6215,3950 7025,3950 7030,3945 7030,3845 7000,3815 6195,3815 6185,3825 6215,3855
GND on Top Layer (solid, remove dead copper, pour order 224): 3770,4295 3840,4295 3840,4245 3835,4240 3770.19,4240 3770.19,4294.81
ISNS+ on Top Layer (solid, remove dead copper, pour order 226): 6560,4775 6565,4775 6570,4780 6586.78,4780 6596.78,4770 6650,4770 6650,4759.56 6599.56,4759.56 6595,4755 6585,4755 6580,4750 6560,4750
GND on Top Layer (solid, remove dead copper, pour order 228): 3050,5585 3050,3000 7220,3000 7220,5585
GND on Top Layer (solid, remove dead copper, pour order 230): 3000,5610 3000,3075 7140,3075 7140,5610

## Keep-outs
Board Outline Layer:
  region: 5529.65,4911.61 5529.65,4738.39 5860.35,4738.39 5860.35,4911.61
  region: 4376.5,4663.03 4376.5,4175 4685,4175 4685,4663.03
  region: 5915,4600 5915,4300 6395,4300 6395,4600
  lines w10: 3195,3280.28 3195,5406.26 cw(c3273.74,5406.26) 3273.74,5485 7013.9,5485 cw(c7013.9,5406.26) 7092.64,5406.26 7092.64,3280.28 cw(c7013.9,3280.28) 7013.9,3201.54 3273.74,3201.54 cw(c3273.74,3280.28) 3195,3280.28

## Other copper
Top Layer:
  region net GND: 3355,5445 3355,5165 4120,5165 4120,5445
  region net GND: 3712.23,4110 3712.23,4169.22 3685,4169.31 3685,4205 3690,4200 3739.59,4200 3727.7,4188.11 3727.14,4110
Inner2 (plane layer: these items are gaps in the copper):
  lines w6: 4950,5385 4950,5240 4960,5230 5060,5230 5053.64,5223.64 5053.64,4804.69 5068.32,4790 5380,4790 5380,4855 5425,4900 5425,5280 5430,5275 5610,5275 5610,5355 5630,5375 5620,5385 4952.27,5385 ; 6218.01,5053.56 6218.56,5053.56 6220,5055 ; 6424.87,4754.43 6435.83,4765.39 6537.91,4765.39 6557.51,4785 6695,4785 6700,4780 6700,4725 6682.58,4713.92 6557.83,4713.92 6551.61,4673.15 6593.8,4618.8 6615,4435 6600,4420 6600,4355 6615,4340 6615,4100 6600,4085 5885,4085 5860,4110 5860,4275 5875,4290 6425,4290 6470,4335 6470,4470 6440,4470 6425,4485 6425,4754.43 ; 4944.97,3448.54 5125,3500 5245,3620 5440,3945 5695,4080 5700,4075 5710,4085 5710,4500 5855,4500 5861.87,4506.87 5861.87,4717.16 5845.43,4733.6 5298.45,4733.6 5135,4570.14 5135,4145 5030,4040 5030,3835 4895,3700 4856.18,3700 4720.43,3564.24 4720.43,3414.57 4668.1,3414.57 4575,3385 4525,3335 4525,3240 4530,3235 4865,3235 4890,3260 4944.97,3448.54 ; 4944.97,3448.54 4945.56,3450.56 4942.97,3447.97 4944.97,3448.54 ; 3240,3250 3464.42,3250 3475,3239.42 3520,3284.42 3520,3785 3530,3795 3825,3795 3845,3775 3845,3510 3937.99,3510 3992.24,3564.24 4021.48,3535 4615,3535 4615,3625 4700,3710 4815,3710 4985,3880 4985,4060 4920,4060 4943.28,4083.28 4943.28,4685 4695,4685 4695,4675 4700,4660 4706.99,4149.59 4691.82,4148.18 4605,4148.18 4605,4036.6 4420,4036.6 4420,4140 4410.41,4149.59 4224.59,4149.59 4150,4075 4150,4065.24 3977.05,3892.28 3497.28,3892.28 3380,3775 3240,3635 3240,3250 ; 5785,3260 5810,3235 6081.78,3235 6095,3248.22 6095,3422.87 6220,3547.87 6220,3955 6968.32,3955 6978.32,3965 6978.32,4344.15 6965,4357.48 6667.48,4357.48 6655,4345 6655,4075 6650,4070 5850,4070 5785,4005 5785,3260 ; 5890,4620 5900,4610 6325,4610 6350,4635 6385,4640 6385,4803.53 6407.05,4825.57 6495.57,4825.57 6515,4845 6515,4859.34 6527.13,4871.47 6593.03,4871.47 6610.45,4854.05 6669.05,4854.05 6685,4870 6685,4896.24 6651.16,4930.08 6581.74,4930.08 6575.59,4936.23 6575.59,5053.56 6215.17,5053.56 6000,5050 5890,4940 5890,4620

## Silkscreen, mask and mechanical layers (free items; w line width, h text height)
Top Silkscreen Layer:
  lines w10: 4005.06,3305 4335,3305 ; 4084.21,3205 4084.21,3405 ; 4170.03,3205 4170.03,3405 ; 4250.87,3205 4250.87,3405 ; 5402.69,5383.9 5732.63,5383.9 ; 5403.9,5382.5 5733.84,5382.5 ; 5404.16,3303.6 5734.09,3303.6 ; 5405.03,3305 5734.97,3305 ; 5405.48,5385 5735.41,5385 ; 5483.05,5282.5 5483.05,5482.5 ; 5483.3,3203.6 5483.3,3403.6 ; 5484.18,3205 5484.18,3405 ; 5486.82,5283.9 5486.82,5483.9 ; 5489.6,5285 5489.6,5485 ; 5567.66,5283.9 5567.66,5483.9 ; 5568.87,5282.5 5568.87,5482.5 ; 5569.12,3203.6 5569.12,3403.6 ; 5570,3205 5570,3405 ; 5570.44,5285 5570.44,5485 ; 5649.71,5282.5 5649.71,5482.5 ; 5649.96,3203.6 5649.96,3403.6 ; 5650.84,3205 5650.84,3405 ; 5653.48,5283.9 5653.48,5483.9 ; 5656.27,5285 5656.27,5485 ; 6550.03,5380 6879.97,5380 ; 6551.24,5378.6 6881.18,5378.6 ; 6618.9,3298.6 6948.84,3298.6 ; 6620.03,3300 6949.97,3300 ; 6630.39,5278.6 6630.39,5478.6 ; 6634.16,5280 6634.16,5480 ; 6698.05,3198.6 6698.05,3398.6 ; 6699.18,3200 6699.18,3400 ; 6715,5280 6715,5480 ; 6716.21,5278.6 6716.21,5478.6 ; 6783.87,3198.6 6783.87,3398.6 ; 6785,3200 6785,3400 ; 6797.05,5278.6 6797.05,5478.6 ; 6800.82,5280 6800.82,5480 ; 6864.71,3198.6 6864.71,3398.6 ; 6865.84,3200 6865.84,3400 ; 4005.06,3205 4005.06,3405 4335,3405 4335,3205 4005.06,3205 ; 5402.69,5283.9 5402.69,5483.9 5732.63,5483.9 5732.63,5283.9 5402.69,5283.9 ; 5403.9,5282.5 5403.9,5482.5 5733.84,5482.5 5733.84,5282.5 5403.9,5282.5 ; 5404.16,3203.6 5404.16,3403.6 5734.09,3403.6 5734.09,3203.6 5404.16,3203.6 ; 5405.03,3205 5405.03,3405 5734.97,3405 5734.97,3205 5405.03,3205 ; 5405.48,5285 5405.48,5485 5735.41,5485 5735.41,5285 5405.48,5285 ; 6550.03,5280 6550.03,5480 6879.97,5480 6879.97,5280 6550.03,5280 ; 6551.24,5278.6 6551.24,5478.6 6881.18,5478.6 6881.18,5278.6 6551.24,5278.6 ; 6618.9,3198.6 6618.9,3398.6 6948.84,3398.6 6948.84,3198.6 6618.9,3198.6 ; 6620.03,3200 6620.03,3400 6949.97,3400 6949.97,3200 6620.03,3200
  text "GND" at 5478.84,5387.5 h50 r90
  text "GND" at 5557.17,5387.5 h50 r90
  text "GND" at 5635.51,5387.5 h50 r90
  text "GND" at 5713.84,5387.5 h50 r90
  text "GND" at 6626.18,5383.6 h50 r90
  text "GND" at 6704.51,5383.6 h50 r90
  text "GND" at 6782.84,5383.6 h50 r90
  text "GND" at 6861.18,5383.6 h50 r90
  text "24V" at 5425.48,5380 h50 r270
  text "24V" at 5503.81,5380 h50 r270
  text "24V" at 5582.14,5380 h50 r270
  text "24V" at 5660.48,5380 h50 r270
  text "12V" at 6701.18,5283.6 h50 r90
  text "12V" at 6623.71,5282.7 h50 r90
  text "12V" at 6780.38,5282.7 h50 r90
  text "12V" at 6858.71,5282.7 h50 r90
  text "24V" at 4080,3310 h50 r90
  text "24V" at 4158.33,3310 h50 r90
  text "24V" at 4236.67,3310 h50 r90
  text "24V" at 4315,3310 h50 r90
  text "12V" at 5479.09,3308.6 h50 r90
  text "12V" at 5557.43,3308.6 h50 r90
  text "12V" at 5635.76,3308.6 h50 r90
  text "12V" at 5714.09,3308.6 h50 r90
  text "5V" at 6693.84,3303.6 h50 r90
  text "5V" at 6772.17,3303.6 h50 r90
  text "5V" at 6850.51,3303.6 h50 r90
  text "5V" at 6928.84,3303.6 h50 r90
  text "GND" at 4155,3210 h50 r90
  text "GND" at 5554.97,3210 h50 r90
  text "GND" at 4077.53,3209.1 h50 r90
  text "GND" at 4234.2,3209.1 h50 r90
  text "GND" at 4312.53,3209.1 h50 r90
  text "GND" at 5477.5,3209.1 h50 r90
  text "GND" at 5554.09,3208.6 h50 r90
  text "GND" at 5634.17,3209.1 h50 r90
  text "GND" at 5712.5,3209.1 h50 r90
  text "GND" at 5476.62,3207.7 h50 r90
  text "GND" at 5633.29,3207.7 h50 r90
  text "GND" at 5711.62,3207.7 h50 r90
  text "GND" at 6769.97,3205 h50 r90
  text "GND" at 6692.5,3204.1 h50 r90
  text "GND" at 6768.84,3203.6 h50 r90
  text "GND" at 6849.17,3204.1 h50 r90
  text "GND" at 6927.5,3204.1 h50 r90
  text "GND" at 6691.37,3202.7 h50 r90
  text "GND" at 6848.04,3202.7 h50 r90
  text "GND" at 6926.37,3202.7 h50 r90
Bottom Silkscreen Layer:
  lines w10: 3600.5,3300 3995,3300 ; 3694.91,3200.79 3694.91,3399.21 ; 3795,3200.79 3795,3399.21 ; 3895,3201.57 3895,3400 ; 4005.06,3205 4005.06,3404.94 4010,3405 4337.32,3405 4337.32,3205 ; 4005.06,3210 4005.06,3202.8 4337.32,3202.8 4337.32,3210 ; 4005.06,3300 4335,3300 ; 4005.06,3329.94 4005.06,3332.65 ; 4084.21,3205 4084.21,3405 ; 4170.03,3205 4170.03,3405 ; 4250.94,3205 4250.94,3405 ; 4999.34,5382.5 5393.84,5382.5 ; 4999.59,3298.6 5394.09,3298.6 ; 5093.75,5283.29 5093.75,5481.71 ; 5094.01,3199.39 5094.01,3397.81 ; 5193.84,5283.29 5193.84,5481.71 ; 5194.09,3199.39 5194.09,3397.81 ; 5293.84,5284.07 5293.84,5482.5 ; 5294.09,3200.18 5294.09,3398.6 ; 5403.9,5287.5 5403.9,5487.44 5408.84,5487.5 5736.16,5487.5 5736.16,5287.5 ; 5403.9,5292.5 5403.9,5285.3 5736.16,5285.3 5736.16,5292.5 ; 5403.9,5382.5 5733.84,5382.5 ; 5403.9,5482.44 5403.9,5485.15 ; 5404.16,3203.6 5404.16,3403.54 5409.09,3403.6 5736.41,3403.6 5736.41,3203.6 ; 5404.16,3208.6 5404.16,3201.4 5736.41,3201.4 5736.41,3208.6 ; 5404.16,3298.6 5734.09,3298.6 ; 5404.16,3323.54 5404.16,3326.26 ; 5483.05,5287.5 5483.05,5487.5 ; 5483.3,3203.6 5483.3,3403.6 ; 5568.87,5287.5 5568.87,5487.5 ; 5569.12,3203.6 5569.12,3403.6 ; 5649.78,5287.5 5649.78,5487.5 ; 5650.03,3203.6 5650.03,3403.6 ; 6146.67,5378.6 6541.18,5378.6 ; 6214.34,3298.6 6608.84,3298.6 ; 6241.09,5279.39 6241.09,5477.81 ; 6308.75,3199.39 6308.75,3397.81 ; 6341.18,5279.39 6341.18,5477.81 ; 6408.84,3199.39 6408.84,3397.81 ; 6441.18,5280.18 6441.18,5478.6 ; 6508.84,3200.18 6508.84,3398.6 ; 6551.24,5283.6 6551.24,5483.54 6556.18,5483.6 6883.5,5483.6 6883.5,5283.6 ; 6551.24,5288.6 6551.24,5281.4 6883.5,5281.4 6883.5,5288.6 ; 6551.24,5378.6 6881.18,5378.6 ; 6551.24,5478.54 6551.24,5481.26 ; 6618.9,3203.6 6618.9,3403.54 6623.84,3403.6 6951.16,3403.6 6951.16,3203.6 ; 6618.9,3208.6 6618.9,3201.4 6951.16,3201.4 6951.16,3208.6 ; 6618.9,3298.6 6948.84,3298.6 ; 6618.9,3323.54 6618.9,3326.26 ; 6630.39,5283.6 6630.39,5483.6 ; 6698.05,3203.6 6698.05,3403.6 ; 6716.21,5283.6 6716.21,5483.6 ; 6783.87,3203.6 6783.87,3403.6 ; 6797.12,5283.6 6797.12,5483.6 ; 6864.78,3203.6 6864.78,3403.6 ; 3595.39,3200 3595.39,3201.57 ; 3595.39,3200 3595.39,3201.57 ; 3595.39,3200 3595.39,3201.57 ; 3595.39,3201.57 3995,3201.57 3995,3405 3595,3405 3595.39,3404.61 3595.39,3201.57 ; 4994.23,5282.5 4994.23,5284.07 ; 4994.23,5282.5 4994.23,5284.07 ; 4994.23,5282.5 4994.23,5284.07 ; 4994.23,5284.07 5393.84,5284.07 5393.84,5487.5 4993.84,5487.5 4994.23,5487.11 4994.23,5284.07 ; 4994.49,3198.6 4994.49,3200.18 ; 4994.49,3198.6 4994.49,3200.18 ; 4994.49,3198.6 4994.49,3200.18 ; 4994.49,3200.18 5394.09,3200.18 5394.09,3403.6 4994.09,3403.6 4994.49,3403.21 4994.49,3200.18 ; 6141.57,5278.6 6141.57,5280.18 ; 6141.57,5278.6 6141.57,5280.18 ; 6141.57,5278.6 6141.57,5280.18 ; 6141.57,5280.18 6541.18,5280.18 6541.18,5483.6 6141.18,5483.6 6141.57,5483.21 6141.57,5280.18 ; 6209.23,3198.6 6209.23,3200.18 ; 6209.23,3198.6 6209.23,3200.18 ; 6209.23,3198.6 6209.23,3200.18 ; 6209.23,3200.18 6608.84,3200.18 6608.84,3403.6 6208.84,3403.6 6209.23,3403.21 6209.23,3200.18
  text "GND" at 5471.34,5473.3 h40 r90
  text "GND" at 5549.67,5473.3 h40 r90
  text "GND" at 5706.34,5473.3 h40 r90
  text "GND" at 5628.87,5472.4 h40 r90
  text "GND" at 6618.68,5469.4 h40 r90
  text "GND" at 6697.01,5469.4 h40 r90
  text "GND" at 6776.21,5468.5 h40 r90
  text "GND" at 6853.68,5469.4 h40 r90
  text "VIN" at 5471.37,5362.19 h40 r90
  text "VIN" at 5549.71,5362.19 h40 r90
  text "VIN" at 5706.37,5362.19 h40 r90
  text "VIN" at 5628.91,5361.29 h40 r90
  text "VIN" at 6618.71,5358.29 h40 r90
  text "VIN" at 6697.04,5358.29 h40 r90
  text "VIN" at 6853.71,5358.29 h40 r90
  text "VIN" at 6776.24,5357.39 h40 r90
  text "48V转24V转12V转5V / DCDC降压模块" at 5855,4570 h200
  text "VOUT" at 4109.97,3306 h40 r270
  text "VOUT" at 4032.5,3305.1 h40 r270
  text "VOUT" at 4189.17,3305.1 h40 r270
  text "VOUT" at 4267.5,3305.1 h40 r270
  text "VOUT" at 5509.06,3304.6 h40 r270
  text "VOUT" at 6723.81,3304.6 h40 r270
  text "VOUT" at 5431.59,3303.7 h40 r270
  text "VOUT" at 5588.26,3303.7 h40 r270
  text "VOUT" at 5666.59,3303.7 h40 r270
  text "VOUT" at 6646.34,3303.7 h40 r270
  text "VOUT" at 6803.01,3303.7 h40 r270
  text "VOUT" at 6881.34,3303.7 h40 r270
  text "GND" at 6646.37,3212.59 h40 r270
  text "GND" at 4110,3209.89 h40 r270
  text "GND" at 4032.53,3208.99 h40 r270
  text "GND" at 4189.2,3208.99 h40 r270
  text "GND" at 4267.53,3208.99 h40 r270
  text "GND" at 5431.62,3207.59 h40 r270
  text "GND" at 5509.09,3208.49 h40 r270
  text "GND" at 5588.29,3207.59 h40 r270
  text "GND" at 5666.62,3207.59 h40 r270
  text "GND" at 6723.84,3208.49 h40 r270
  text "GND" at 6803.04,3207.59 h40 r270
  text "GND" at 6881.37,3207.59 h40 r270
